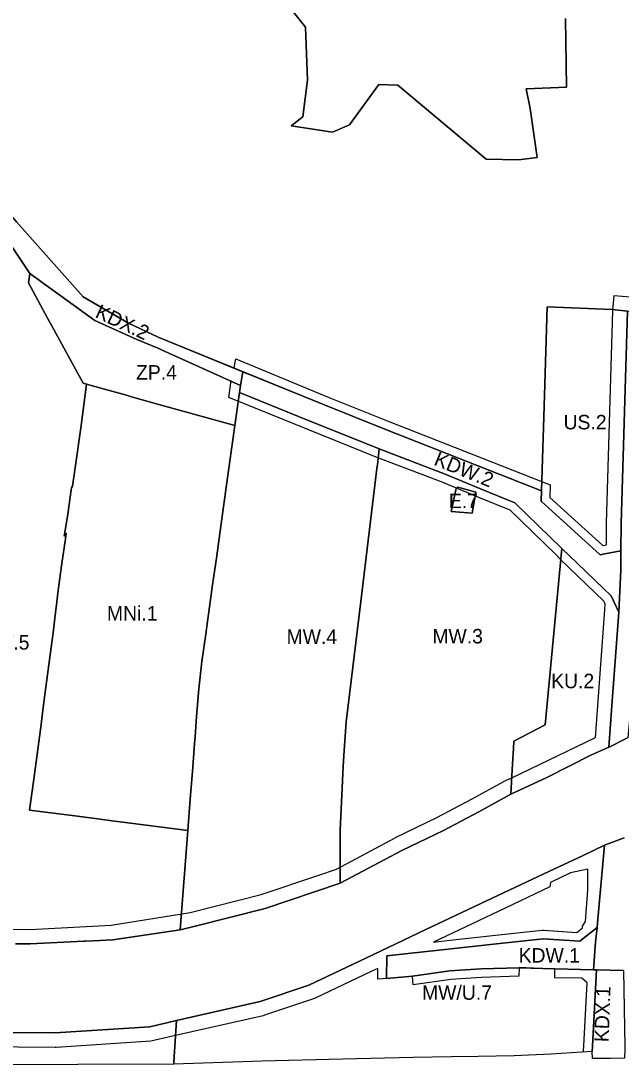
# Model space of a CAD drawing. Extents: x 7421913 to 7423341, y 5550123 to 5551175.
# Drawn here: x 7422620.4 to 7422827.7, y 5550123.5 to 5550484.1 of the extents above; entities that cross this region are included whole.
import ezdxf

# ---------------------------------------------------------------- set-up
doc = ezdxf.new("R2010")
doc.units = 0
for name, color, linetype in [('linie_rozgraniczajace', 7, 'Continuous'), ('linie_zabudowy_nieprzekraczalne', 7, 'Continuous'), ('oznaczenia_przeznaczen', 7, 'Continuous')]:
    doc.layers.add(name, color=color, linetype=linetype)

msp = doc.modelspace()

# ---------------------------------------------------------------- linework, layer by layer
at = {"layer": 'linie_rozgraniczajace'}
for points in [[(7422695.28, 5550511.38), (7422718.75, 5550481.94), (7422719.35, 5550463.56), (7422717.84, 5550450.96), (7422713.79, 5550447.78), (7422728.01, 5550445.61), (7422733.92, 5550448.14), (7422744.07, 5550462.11), (7422750.61, 5550461.86), (7422781.1, 5550436.26), (7422792.28, 5550436.05), (7422798.68, 5550436.92), (7422796.29, 5550453.84), (7422794.93, 5550460.64), (7422808.82, 5550461.16), (7422808.51, 5550484.83)], [(7422808.51, 5550484.83), (7422808.82, 5550461.16), (7422794.93, 5550460.64), (7422796.29, 5550453.84), (7422798.68, 5550436.92), (7422792.28, 5550436.05), (7422781.1, 5550436.26), (7422750.61, 5550461.86), (7422744.07, 5550462.11), (7422733.92, 5550448.14), (7422728.01, 5550445.61), (7422713.79, 5550447.78), (7422717.84, 5550450.96), (7422719.35, 5550463.56), (7422718.75, 5550481.94), (7422695.28, 5550511.38)], [(7422829.89, 5550383.84), (7422824.62, 5550384.35), (7422802.12, 5550385.36), (7422801.25, 5550354.66), (7422800.25, 5550321.84), (7422746.13, 5550343.06), (7422725.45, 5550351.34), (7422717.51, 5550354.58), (7422667.8, 5550374.88), (7422657.58, 5550379.72), (7422641.94, 5550388.78), (7422618.97, 5550414.72), (7422611.54, 5550423.13), (7422570.5, 5550445.27), (7422562.27, 5550456.27), (7422563.21, 5550461.08), (7422568.23, 5550485.99)], [(7422611.65, 5550414.43), (7422623.5, 5550396.81), (7422623.03, 5550393.58), (7422629.66, 5550381.42), (7422631.21, 5550378.58), (7422641.95, 5550358.91), (7422643.14, 5550358.58), (7422641.29, 5550344.4), (7422639.05, 5550328.88), (7422638.29, 5550323.41), (7422637.9, 5550322.8), (7422637.79, 5550322.1), (7422636.62, 5550313.78), (7422636.59, 5550313.59), (7422635.43, 5550306.19), (7422636.05, 5550307.16), (7422635.78, 5550305.22), (7422634.61, 5550296.74), (7422633.42, 5550288.32), (7422633.31, 5550287.35), (7422632.65, 5550281.45), (7422632.31, 5550278.88), (7422631.52, 5550272.78), (7422631.09, 5550269.46), (7422629.86, 5550260.01), (7422628.63, 5550250.55), (7422627.93, 5550245.16), (7422627.39, 5550241.15), (7422626.11, 5550231.63), (7422624.85, 5550222.21), (7422623.43, 5550211.51), (7422639.03, 5550209.52), (7422647.8, 5550208.4), (7422652.76, 5550207.77), (7422654.74, 5550207.52), (7422678.1, 5550204.55), (7422675.46, 5550170.18), (7422652.14, 5550166.79), (7422649.77, 5550166.66), (7422647.8, 5550166.56), (7422642.6, 5550166.29), (7422642.21, 5550166.27), (7422623.63, 5550165.32), (7422618.56, 5550165.36)], [(7422618.56, 5550165.36), (7422623.63, 5550165.32), (7422642.21, 5550166.27), (7422642.6, 5550166.29), (7422647.8, 5550166.56), (7422649.77, 5550166.66), (7422652.14, 5550166.79), (7422675.46, 5550170.18), (7422680.12, 5550171.34), (7422704.82, 5550177.55), (7422730.73, 5550186.28), (7422751.99, 5550197.6), (7422766.33, 5550204.54), (7422778.59, 5550211), (7422789.58, 5550217.04), (7422802, 5550222.78), (7422817.26, 5550230.54), (7422823.48, 5550233.26), (7422823.84, 5550233.41), (7422829.17, 5550236.11)], [(7422828.8, 5550202.01), (7422821.96, 5550199.46), (7422814.62, 5550195.9), (7422801.01, 5550189.55), (7422783.13, 5550181.09), (7422760.26, 5550170.26), (7422739.51, 5550160.44), (7422719.88, 5550151.07), (7422703.01, 5550145.43), (7422674.14, 5550138.95), (7422665, 5550136.74), (7422632.27, 5550134.58), (7422606.41, 5550134.79)], [(7422828.58, 5550156.17), (7422819.24, 5550156.38), (7422818.15, 5550156.4), (7422818.9, 5550165.93), (7422819.4, 5550171.06), (7422819.54, 5550172.67), (7422821.96, 5550199.46), (7422828.8, 5550202.01)]]:
    msp.add_lwpolyline(points, dxfattribs=at)
for points in [[(7422697.12, 5550362.91), (7422696.25, 5550358.21), (7422676.08, 5550367.3), (7422669.24, 5550370.39), (7422668.01, 5550370.94), (7422660.44, 5550374.09), (7422646.02, 5550380.62), (7422623.5, 5550396.81), (7422611.65, 5550414.43), (7422608.96, 5550418.42), (7422611.54, 5550423.13), (7422618.97, 5550414.72), (7422641.94, 5550388.78), (7422657.58, 5550379.72), (7422667.8, 5550374.88)], [(7422695.9, 5550355.7), (7422694.32, 5550344.4), (7422666.04, 5550352.23), (7422658.64, 5550354.28), (7422656.87, 5550354.77), (7422649.33, 5550356.87), (7422643.14, 5550358.58), (7422641.95, 5550358.91), (7422631.21, 5550378.58), (7422629.66, 5550381.42), (7422623.03, 5550393.58), (7422623.5, 5550396.81), (7422646.02, 5550380.62), (7422660.44, 5550374.09), (7422668.01, 5550370.94), (7422669.24, 5550370.39), (7422676.08, 5550367.3), (7422696.25, 5550358.21)], [(7422829.89, 5550383.84), (7422827.71, 5550310.51), (7422827.61, 5550301.08), (7422822.03, 5550299.98), (7422820.48, 5550299.68), (7422800.07, 5550318.2), (7422800.25, 5550321.84), (7422801.25, 5550354.66), (7422802.12, 5550385.36), (7422824.62, 5550384.35)], [(7422843.85, 5550382.56), (7422843.62, 5550382.15), (7422836.75, 5550373.03), (7422836.36, 5550360.07), (7422836.02, 5550349.03), (7422833.97, 5550277.87), (7422833.54, 5550273.26), (7422830.54, 5550241.46), (7422830.07, 5550236.54), (7422829.17, 5550236.11), (7422823.84, 5550233.41), (7422823.48, 5550233.26), (7422824.63, 5550249.17), (7422826.86, 5550279.87), (7422827.55, 5550294.36), (7422827.61, 5550300.64), (7422827.61, 5550301.08), (7422827.71, 5550310.51), (7422829.89, 5550383.84), (7422830.3, 5550383.8), (7422837.06, 5550383.25)], [(7422800.25, 5550321.84), (7422800.07, 5550318.2), (7422820.48, 5550299.68), (7422822.03, 5550299.98), (7422827.61, 5550301.08), (7422827.61, 5550300.64), (7422827.55, 5550294.36), (7422826.86, 5550279.87), (7422824.23, 5550285.5), (7422821.6, 5550288.04), (7422812.65, 5550296.7), (7422807.25, 5550301.92), (7422791.03, 5550317.61), (7422779.16, 5550322.5), (7422766.98, 5550327.53), (7422744.2, 5550336.26), (7422716.29, 5550347.49), (7422695.9, 5550355.7), (7422696.25, 5550358.21), (7422697.12, 5550362.91), (7422717.51, 5550354.58), (7422725.45, 5550351.34), (7422746.13, 5550343.06)], [(7422684.86, 5550276.65), (7422684.25, 5550272.27), (7422682.94, 5550262.86), (7422681.85, 5550253.39), (7422681.12, 5550243.87), (7422680.58, 5550236.87), (7422680.39, 5550234.4), (7422679.66, 5550224.82), (7422678.93, 5550215.33), (7422678.1, 5550204.55), (7422654.74, 5550207.52), (7422652.76, 5550207.77), (7422647.8, 5550208.4), (7422639.03, 5550209.52), (7422623.43, 5550211.51), (7422624.85, 5550222.21), (7422626.11, 5550231.63), (7422627.39, 5550241.15), (7422627.93, 5550245.16), (7422628.63, 5550250.55), (7422629.86, 5550260.01), (7422631.09, 5550269.46), (7422631.52, 5550272.78), (7422632.31, 5550278.88), (7422632.65, 5550281.45), (7422633.31, 5550287.35), (7422633.42, 5550288.32), (7422634.61, 5550296.74), (7422635.78, 5550305.22), (7422636.05, 5550307.16), (7422635.43, 5550306.19), (7422636.59, 5550313.59), (7422636.62, 5550313.78), (7422637.79, 5550322.1), (7422637.9, 5550322.8), (7422638.29, 5550323.41), (7422639.05, 5550328.88), (7422641.29, 5550344.4), (7422643.14, 5550358.58), (7422649.33, 5550356.87), (7422656.87, 5550354.77), (7422658.64, 5550354.28), (7422666.04, 5550352.23), (7422694.32, 5550344.4), (7422691.45, 5550323.87), (7422690.38, 5550316.21), (7422690.28, 5550315.43), (7422689.1, 5550307), (7422687.93, 5550298.59), (7422686.74, 5550290.09), (7422685.57, 5550281.68)], [(7422695.9, 5550355.7), (7422716.29, 5550347.49), (7422744.2, 5550336.26), (7422743.53, 5550330.77), (7422743.39, 5550329.51), (7422737.84, 5550283.62), (7422732.77, 5550242.06), (7422731.95, 5550230.42), (7422731.68, 5550226.55), (7422730.9, 5550209.5), (7422730.67, 5550204.59), (7422730.68, 5550203.74), (7422730.73, 5550189.15), (7422730.73, 5550186.28), (7422704.82, 5550177.55), (7422680.12, 5550171.34), (7422675.46, 5550170.18), (7422678.1, 5550204.55), (7422678.93, 5550215.33), (7422679.66, 5550224.82), (7422680.39, 5550234.4), (7422680.58, 5550236.87), (7422681.12, 5550243.87), (7422681.85, 5550253.39), (7422682.94, 5550262.86), (7422684.25, 5550272.27), (7422684.86, 5550276.65), (7422685.57, 5550281.68), (7422686.74, 5550290.09), (7422687.93, 5550298.59), (7422689.1, 5550307), (7422690.28, 5550315.43), (7422690.38, 5550316.21), (7422691.45, 5550323.87), (7422694.32, 5550344.4)], [(7422766.98, 5550327.53), (7422779.16, 5550322.5), (7422791.03, 5550317.61), (7422807.25, 5550301.92), (7422801.44, 5550240.99), (7422790.66, 5550235.37), (7422790.51, 5550232.86), (7422790.2, 5550227.5), (7422789.58, 5550217.04), (7422778.59, 5550211), (7422766.33, 5550204.54), (7422751.99, 5550197.6), (7422730.73, 5550186.28), (7422730.73, 5550189.15), (7422730.68, 5550203.74), (7422730.67, 5550204.59), (7422730.9, 5550209.5), (7422731.68, 5550226.55), (7422731.95, 5550230.42), (7422732.77, 5550242.06), (7422737.84, 5550283.62), (7422743.39, 5550329.51), (7422743.53, 5550330.77), (7422744.2, 5550336.26)], [(7422776.25, 5550314.13), (7422777.53, 5550321.36), (7422775.93, 5550321.8), (7422771.28, 5550323.09), (7422770.7, 5550322.56), (7422768.98, 5550314.65)], [(7422777.53, 5550321.36), (7422776.25, 5550314.13), (7422768.98, 5550314.65), (7422770.7, 5550322.56), (7422771.28, 5550323.09), (7422775.93, 5550321.8)], [(7422826.86, 5550279.87), (7422824.63, 5550249.17), (7422823.48, 5550233.26), (7422817.26, 5550230.54), (7422802, 5550222.78), (7422789.58, 5550217.04), (7422790.2, 5550227.5), (7422790.51, 5550232.86), (7422790.66, 5550235.37), (7422801.44, 5550240.99), (7422807.25, 5550301.92), (7422812.65, 5550296.7), (7422821.6, 5550288.04), (7422824.23, 5550285.5)], [(7422819.4, 5550171.06), (7422813.43, 5550166.27), (7422800.77, 5550167.05), (7422783.6, 5550165.21), (7422767.95, 5550163.51), (7422754.13, 5550162.02), (7422746.76, 5550161.23), (7422746.7, 5550153.4), (7422755.64, 5550154.15), (7422768.58, 5550156.06), (7422779.35, 5550156.69), (7422792.45, 5550157.12), (7422804.87, 5550156.68), (7422818.15, 5550156.4), (7422819.24, 5550156.38), (7422817.83, 5550130.03), (7422817.74, 5550128.18), (7422803.4, 5550127.23), (7422790.76, 5550126.69), (7422778.3, 5550126.48), (7422769.16, 5550126.34), (7422755.84, 5550126.12), (7422731.51, 5550125.5), (7422703.71, 5550124.8), (7422673.22, 5550123.8), (7422673.27, 5550124.6), (7422674.14, 5550138.95), (7422703.01, 5550145.43), (7422719.88, 5550151.07), (7422739.51, 5550160.44), (7422760.26, 5550170.26), (7422783.13, 5550181.09), (7422801.01, 5550189.55), (7422814.62, 5550195.9), (7422821.96, 5550199.46), (7422819.54, 5550172.67)], [(7422818.15, 5550156.4), (7422804.87, 5550156.68), (7422792.45, 5550157.12), (7422779.35, 5550156.69), (7422768.58, 5550156.06), (7422755.64, 5550154.15), (7422746.7, 5550153.4), (7422746.76, 5550161.23), (7422754.13, 5550162.02), (7422767.95, 5550163.51), (7422783.6, 5550165.21), (7422800.77, 5550167.05), (7422813.43, 5550166.27), (7422819.4, 5550171.06), (7422818.9, 5550165.93)], [(7422828.88, 5550125.92), (7422824.03, 5550125.79), (7422817.81, 5550125.8), (7422817.74, 5550128.18), (7422817.83, 5550130.03), (7422819.24, 5550156.38), (7422828.58, 5550156.17), (7422829.02, 5550129.76), (7422829.03, 5550128.94)], [(7422674.14, 5550138.95), (7422673.27, 5550124.6), (7422673.22, 5550123.8), (7422606.86, 5550123.56), (7422587.22, 5550123.49), (7422518.12, 5550125.17), (7422463.31, 5550126.5), (7422433.05, 5550127.24), (7422435.11, 5550129.05), (7422436.24, 5550130.04), (7422443.14, 5550136.08), (7422487.48, 5550135.63), (7422517.47, 5550135.44), (7422532.53, 5550135.35), (7422544.63, 5550135.28), (7422573.63, 5550135.06), (7422589.48, 5550134.93), (7422600.04, 5550134.84), (7422606.41, 5550134.79), (7422632.27, 5550134.58), (7422665, 5550136.74)]]:
    msp.add_lwpolyline(points, close=True, dxfattribs=at)
at = {"layer": 'linie_zabudowy_nieprzekraczalne'}
for points in [[(7422694.08, 5550364.23), (7422694.62, 5550367.4), (7422726.57, 5550354.12), (7422747.24, 5550345.85), (7422803.22, 5550323.91), (7422803.14, 5550319.47), (7422821.38, 5550302.91), (7422821.45, 5550302.93), (7422822.64, 5550303.16), (7422822.71, 5550310.56), (7422822.71, 5550310.66), (7422824.89, 5550383.99), (7422824.9, 5550384.17), (7422825.29, 5550389.26), (7422848.79, 5550387.25)], [(7422806.8, 5550298.05), (7422805.16, 5550299.76), (7422789.36, 5550315.06), (7422778.02, 5550319.73), (7422765.87, 5550324.74), (7422743.17, 5550333.44), (7422692.21, 5550354.07), (7422693.04, 5550359.88)], [(7422613.94, 5550170.41), (7422623.52, 5550170.32), (7422651.64, 5550171.77), (7422678.91, 5550176.19), (7422703.41, 5550182.35), (7422723.36, 5550189.04), (7422729.4, 5550191.15), (7422749.64, 5550202.01), (7422749.78, 5550202.08), (7422749.81, 5550202.1), (7422764.07, 5550209), (7422776.22, 5550215.4), (7422787.17, 5550221.42), (7422787.37, 5550221.52), (7422789.92, 5550222.7), (7422818.85, 5550236.6), (7422822.06, 5550280.69), (7422822.18, 5550282.8), (7422821.75, 5550283.72), (7422806.8, 5550298.05)], [(7422816.19, 5550191.11), (7422810.26, 5550189.92), (7422803.35, 5550186.51), (7422803.14, 5550185.02), (7422785.27, 5550176.57), (7422762.91, 5550165.98), (7422767.63, 5550166.49), (7422783.28, 5550168.19), (7422783.28, 5550168.19), (7422800.45, 5550170.03), (7422800.57, 5550170.04), (7422800.77, 5550170.05), (7422800.95, 5550170.04), (7422812.46, 5550169.33), (7422814.36, 5550170.86), (7422814.42, 5550171.52), (7422815.42, 5550173.05), (7422816.16, 5550183.93), (7422816.19, 5550191.11)], [(7422814.74, 5550127.98), (7422814.74, 5550128.1), (7422814.74, 5550128.18), (7422814.74, 5550128.33), (7422814.83, 5550130.18), (7422814.83, 5550130.19), (7422816, 5550151.89), (7422815.94, 5550151.92), (7422814.09, 5550153.49), (7422804.81, 5550153.68), (7422804.76, 5550153.68), (7422804.82, 5550156.65), (7422792.47, 5550157.2), (7422792.38, 5550154.25), (7422779.49, 5550153.69), (7422768.89, 5550153.07), (7422755.89, 5550151.16), (7422755.64, 5550154.15), (7422746.7, 5550153.44), (7422743.71, 5550153.2), (7422743.73, 5550156.9), (7422741.66, 5550155.92), (7422722.03, 5550146.56), (7422721.79, 5550146.45), (7422721.49, 5550146.34), (7422721.47, 5550146.33), (7422704.6, 5550140.69), (7422704.3, 5550140.6), (7422704.1, 5550140.55), (7422673.78, 5550133.76)], [(7422673.78, 5550133.76), (7422665.33, 5550131.75), (7422632.6, 5550129.59), (7422632.25, 5550129.58), (7422606.37, 5550129.79), (7422573.59, 5550130.06), (7422544.6, 5550130.28), (7422487.44, 5550130.63), (7422445, 5550131.06), (7422437.58, 5550131.21)]]:
    msp.add_lwpolyline(points, dxfattribs=at)

# ---------------------------------------------------------------- texts
at = {"layer": 'oznaczenia_przeznaczen'}
for s, rotation, p in [('KDX.2', 335.0169, (7422645.73, 5550381.84)), ('KDW.2', 337.9386, (7422762.72, 5550330.84)), ('KDX.1', 87.9916, (7422823.39, 5550131.36))]:
    msp.add_text(s, height=5, rotation=rotation, dxfattribs=at).set_placement(p)
for s, p in [('ZP.4', (7422660.19, 5550360.18)), ('US.2', (7422807.82, 5550343.01)), ('E.7', (7422768.21, 5550315.81)), ('MNi.1', (7422650.15, 5550276.98)), ('MW.5', (7422605.94, 5550266.96)), ('MW.4', (7422712.18, 5550268.93)), ('MW.3', (7422762.52, 5550269.1)), ('KU.2', (7422803.53, 5550253.62)), ('KDW.1', (7422792.31, 5550158.9)), ('MW/U.7', (7422758.96, 5550146.05))]:
    msp.add_text(s, height=5, dxfattribs=at).set_placement(p)

doc.saveas('drawing.dxf')
